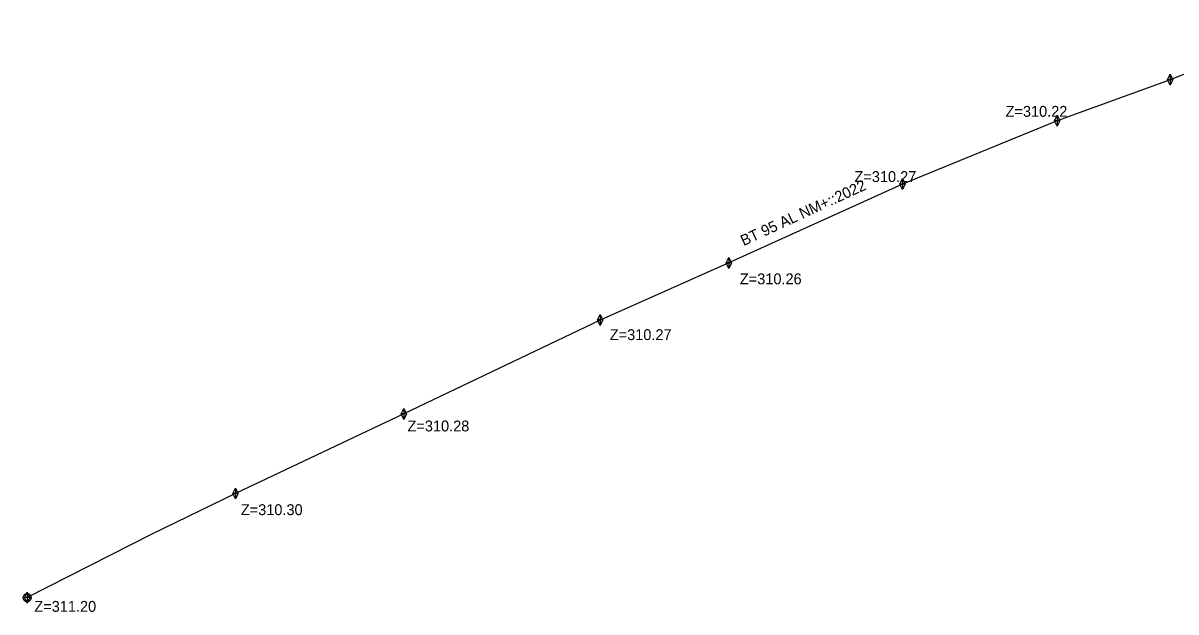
# Model space of a CAD drawing. Extents: x 799271 to 799523, y 67737 to 68184.
# Drawn here: x 799271.4 to 799313.83, y 68117.48 to 68139.16 of the extents above; entities that cross this region are included whole.
import ezdxf

# ---------------------------------------------------------------- set-up
doc = ezdxf.new("R2010")
doc.units = 0
doc.layers.add('PGOC_BT_CONSTRUIT', color=7, linetype='Continuous')
doc.layers.add('PGOC_PTRL', color=7, linetype='Continuous')

msp = doc.modelspace()

# ---------------------------------------------------------------- linework, layer by layer
at = {"layer": 'PGOC_BT_CONSTRUIT'}
msp.add_lwpolyline([(799325.695, 68133.935), (799325.714, 68134.244), (799325.72, 68134.356), (799325.523, 68134.562), (799325.287, 68134.766), (799320.298, 68138.654), (799319.918, 68138.897), (799319.629, 68139.051), (799319.267, 68139.164), (799318.707, 68139.081), (799313.619, 68137.078), (799309.462, 68135.566), (799303.767, 68133.234), (799297.376, 68130.329), (799292.64, 68128.222), (799285.412, 68124.768), (799279.22, 68121.838), (799276.144, 68120.348), (799271.55, 68118.005), (799271.55, 68118.005), (799271.55, 68118.005)], dxfattribs=at)
msp.add_circle((799271.55, 68118.005), 0.15, dxfattribs=at)
at = {"layer": 'PGOC_PTRL'}
for points in [[(799313.519, 68137.078), (799313.619, 68137.278), (799313.719, 68137.078), (799313.619, 68136.878), (799313.519, 68137.078)], [(799313.619, 68137.278), (799313.619, 68136.878)], [(799313.719, 68137.078), (799313.619, 68137.078), (799313.519, 68137.078)], [(799309.362, 68135.566), (799309.462, 68135.766), (799309.562, 68135.566), (799309.462, 68135.366), (799309.362, 68135.566)], [(799309.562, 68135.566), (799309.462, 68135.566), (799309.362, 68135.566)], [(799309.462, 68135.766), (799309.462, 68135.366)], [(799303.667, 68133.234), (799303.767, 68133.434), (799303.867, 68133.234), (799303.767, 68133.034), (799303.667, 68133.234)], [(799303.767, 68133.434), (799303.767, 68133.034)], [(799303.867, 68133.234), (799303.767, 68133.234), (799303.667, 68133.234)], [(799297.276, 68130.329), (799297.376, 68130.529), (799297.476, 68130.329), (799297.376, 68130.129), (799297.276, 68130.329)], [(799297.376, 68130.529), (799297.376, 68130.129)], [(799297.476, 68130.329), (799297.376, 68130.329), (799297.276, 68130.329)], [(799292.54, 68128.232), (799292.64, 68128.432), (799292.74, 68128.232), (799292.64, 68128.032), (799292.54, 68128.232)], [(799292.64, 68128.432), (799292.64, 68128.032)], [(799292.74, 68128.232), (799292.64, 68128.232), (799292.54, 68128.232)], [(799285.312, 68124.768), (799285.412, 68124.968), (799285.512, 68124.768), (799285.412, 68124.568), (799285.312, 68124.768)], [(799285.412, 68124.968), (799285.412, 68124.568)], [(799285.512, 68124.768), (799285.412, 68124.768), (799285.312, 68124.768)], [(799279.12, 68121.838), (799279.22, 68122.038), (799279.32, 68121.838), (799279.22, 68121.638), (799279.12, 68121.838)], [(799279.22, 68122.038), (799279.22, 68121.638)], [(799279.32, 68121.838), (799279.22, 68121.838), (799279.12, 68121.838)], [(799271.45, 68118.005), (799271.55, 68118.205), (799271.65, 68118.005), (799271.55, 68117.805), (799271.45, 68118.005)], [(799271.55, 68118.205), (799271.55, 68117.805)], [(799271.65, 68118.005), (799271.55, 68118.005), (799271.45, 68118.005)]]:
    msp.add_lwpolyline(points, dxfattribs=at)

# ---------------------------------------------------------------- texts
at = {"layer": 'PGOC_BT_CONSTRUIT'}
msp.add_text('BT 95 AL NM+::2022', height=0.4, rotation=24.7988, dxfattribs=at).set_placement((799297.919, 68130.947))
at = {"layer": 'PGOC_PTRL'}
for s, p in [('Z=310.22', (799307.559, 68135.712)), ('Z=310.27', (799301.998, 68133.31)), ('Z=310.26', (799297.78, 68129.544)), ('Z=310.27', (799292.993, 68127.49)), ('Z=310.28', (799285.549, 68124.126)), ('Z=310.30', (799279.414, 68121.044)), ('Z=311.20', (799271.816, 68117.483))]:
    msp.add_text(s, height=0.4, dxfattribs=at).set_placement(p)

doc.saveas('drawing.dxf')
